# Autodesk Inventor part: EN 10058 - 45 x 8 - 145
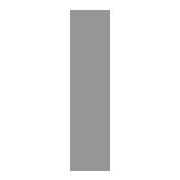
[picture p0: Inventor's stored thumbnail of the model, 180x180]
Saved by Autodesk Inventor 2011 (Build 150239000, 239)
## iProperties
_CCFamilyMember: 49
_CCFamilyDisplayName: DIN EN 10058 - Hot rolled flat steel bars for general purposes
_FrameMemberDoc: Frame Member File
_Version: 15.0.0
_GetPNFromCC: 1
Created: 2010-02
Part Number: EN 10058 - 45 x 8 - 145
Material: Steel, Mild
Description: flat steel bar 45*8
Document SubType Name: Modeling
Standard: DIN
Designer: PC
Standard Revision: 2004
Standards Organization: DIN
Language: en-US
Size Designation: 45 x 8
Categories: <MemberInstance><Categories><Category DisplayName="Structural Shapes" InternalName="089c4875-fa83-4c05-b084-43b9cc11f5ed" Mnemonic="GRDR"><CategoryParameter Dis
Stock Number: 45 x 8
Density: 7.86 g/cm^3
G_L: 145.000 mm
G_W: 8.000 mm
G_H: 45.000 mm
Author: PC
IsCustomPart: 1
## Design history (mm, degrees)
node "Start plane"
node "End plane"
sketch "Sketch"
  geometry: L1 (4, -22.5)-(-4, -22.5); L2 (-4, -22.5)-(-4, 22.5); L3 (-4, 22.5)-(4, 22.5); L4 (4, 22.5)-(4, -22.5); L5 (-6, 0)-(8, 0); L6 (0, -30)-(0, 40); L7 (0, 54)-(0, -44) reference; L8 (-9.2, 0)-(13.2, 0) reference
  constraints: 12 end point, 2 collinear, 2 parallel, 1 horizontal, 1 perpendicular
  dimensions: "d0" = 45 distance between parallel lines of L3 L1 (= G_W); "d1" = 8 distance between parallel lines of L4 L2 (= G_H); "d4" = 4 distance between parallel lines of L6 L4 (= 0.5 x d1); "d5" = 22.5 distance between parallel lines of L5 L3 (= 0.5 x d0)
extrude "Body" new body sketch "Sketch" stored distance "d2" = 145 (= G_L); taper "d3" = 0 deg
node "Driven Length"
  sketch "Sketch3"
    geometry: L1 (0, 0)-(10, 0) reference
    constraints: 2 end point, 1 horizontal
  workplane "Work Plane3"
  sketch "Sketch4"
    geometry: L1 (-2, 0)-(12, 0) reference; L2 (-2, 145)-(12, 145) reference
    dimensions: "d9" = 145 distance between parallel lines of L1 L2 (derived)
body "Solid1"
other parameters: "G_W" = 45 [user parameter; used in 1 equation term], "G_H" = 8 [user parameter; used in 1 equation term], "G_L" = 145 (= d9) [user parameter; used in 1 equation term], "G_OFFSET_START" = 0 [user parameter; used in 1 equation term], "G_OFFSET_END" = 0 [user parameter; used in 1 equation term], "d6" = 0 (computed from G_OFFSET_START), "d7" = 145 (= G_OFFSET_END + B_L), "B_L" = 145 [user parameter; used in 1 equation term], "d8" = 90 deg, "MAS" = 0.283 [user parameter]
